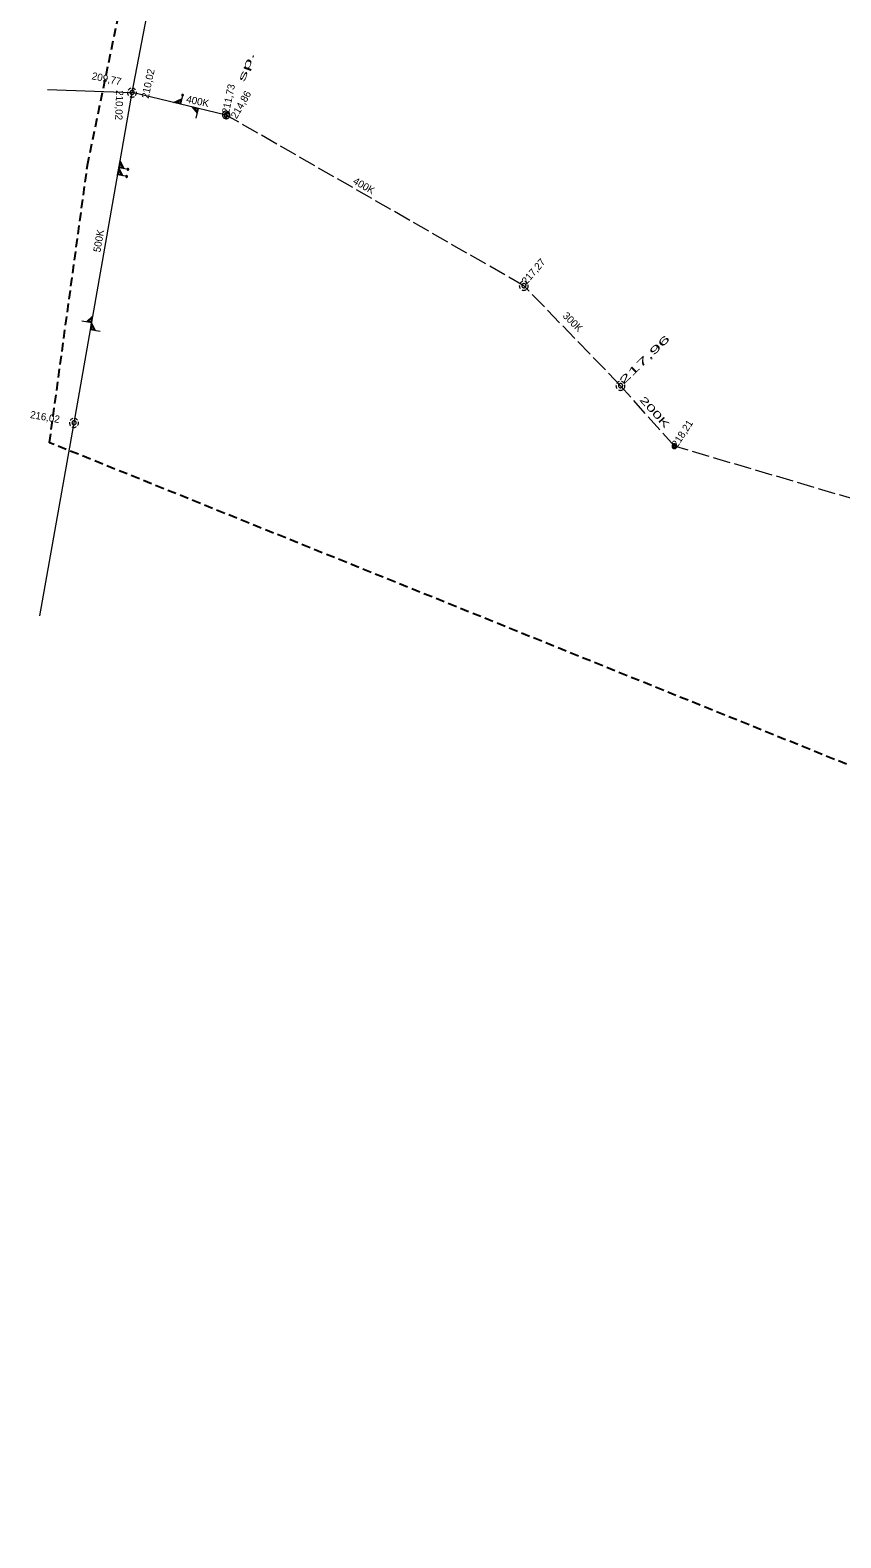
# Model space of a CAD drawing. Extents: x -739741 to -739027, y -1046215 to -1045797.
# Drawn here: x -739740.5 to -739651.7, y -1046072.8 to -1045907.7 of the extents above; entities that cross this region are included whole.
import ezdxf

# ---------------------------------------------------------------- set-up
doc = ezdxf.new("R2010")
doc.units = 0
doc.header["$LTSCALE"] = 0.32
doc.linetypes.add('LONG_DASHED', pattern=[7.5, 6, -1.5])
doc.linetypes.add('MEDIUM_DASHED', pattern=[4.5, 3, -1.5])
doc.layers.add('1', color=7, linetype='Continuous')
for name, color, linetype, lineweight in [('18', 7, 'Continuous', 13), ('20', 7, 'Continuous', 13), ('63', 7, 'MEDIUM_DASHED', 25)]:
    doc.layers.add(name, color=color, linetype=linetype, lineweight=lineweight)

msp = doc.modelspace()

# ---------------------------------------------------------------- linework, layer by layer
at = {"layer": '18'}
msp.add_line((-739719.059, -1045916.633), (-739719.059, -1045917.321), dxfattribs=at)
for points in [[(-739729.857, -1045914.429), (-739729.863, -1045914.506), (-739729.858, -1045914.583), (-739729.841, -1045914.658), (-739729.812, -1045914.729), (-739729.772, -1045914.795), (-739729.756, -1045914.817)], [(-739729.512, -1045914.037), (-739729.583, -1045914.065), (-739729.65, -1045914.104), (-739729.71, -1045914.152), (-739729.761, -1045914.209), (-739729.785, -1045914.243)], [(-739729.599, -1045914.946), (-739729.529, -1045914.977), (-739729.454, -1045914.996), (-739729.378, -1045915.003), (-739729.301, -1045914.998), (-739729.226, -1045914.981), (-739729.154, -1045914.953), (-739729.094, -1045914.918)], [(-739728.971, -1045914.22), (-739729.021, -1045914.162), (-739729.079, -1045914.112), (-739729.144, -1045914.071), (-739729.215, -1045914.042), (-739729.264, -1045914.028)], [(-739728.976, -1045914.806), (-739728.935, -1045914.741), (-739728.904, -1045914.671), (-739728.885, -1045914.596), (-739728.877, -1045914.52), (-739728.882, -1045914.443), (-739728.888, -1045914.408)], [(-739723.813, -1045914.693), (-739724.067, -1045915.758), (-739724.816, -1045915.579), (-739723.933, -1045915.196)], [(-739724.009, -1045915.299), (-739724.106, -1045915.704), (-739724.656, -1045915.572), (-739724.009, -1045915.298)], [(-739722.331, -1045917.302), (-739722.077, -1045916.236), (-739722.827, -1045916.057), (-739722.211, -1045916.798)], [(-739722.233, -1045916.672), (-739722.137, -1045916.267), (-739722.686, -1045916.136), (-739722.234, -1045916.673)], [(-739719.194, -1045917.147), (-739719.172, -1045917.18), (-739719.141, -1045917.205), (-739719.104, -1045917.219), (-739719.065, -1045917.222), (-739719.026, -1045917.213), (-739718.992, -1045917.193), (-739718.966, -1045917.163), (-739718.949, -1045917.127), (-739718.944, -1045917.088), (-739718.951, -1045917.049), (-739718.969, -1045917.014), (-739718.997, -1045916.986), (-739719.032, -1045916.967), (-739719.064, -1045916.96)], [(-739718.935, -1045916.78), (-739718.955, -1045916.747), (-739718.984, -1045916.721), (-739719.02, -1045916.704), (-739719.06, -1045916.7), (-739719.098, -1045916.707), (-739719.133, -1045916.726), (-739719.161, -1045916.754), (-739719.179, -1045916.789), (-739719.185, -1045916.828), (-739719.18, -1045916.867), (-739719.163, -1045916.903), (-739719.136, -1045916.932), (-739719.102, -1045916.951), (-739719.064, -1045916.96)], [(-739729.86, -1045923.711), (-739730.938, -1045923.521), (-739730.805, -1045922.763), (-739730.369, -1045923.621)], [(-739730.477, -1045923.552), (-739730.886, -1045923.48), (-739730.788, -1045922.922), (-739730.476, -1045923.552)], [(-739730.551, -1045923.491), (-739730.839, -1045923.44), (-739730.774, -1045923.074), (-739730.551, -1045923.492)], [(-739729.722, -1045922.927), (-739730.8, -1045922.737), (-739730.667, -1045921.979), (-739730.231, -1045922.837)], [(-739730.339, -1045922.768), (-739730.748, -1045922.696), (-739730.65, -1045922.138), (-739730.338, -1045922.768)], [(-739730.413, -1045922.707), (-739730.701, -1045922.656), (-739730.636, -1045922.29), (-739730.413, -1045922.708)], [(-739686.947, -1045935.589), (-739686.953, -1045935.666), (-739686.948, -1045935.743), (-739686.931, -1045935.818), (-739686.902, -1045935.889), (-739686.862, -1045935.955), (-739686.846, -1045935.977)], [(-739686.602, -1045935.197), (-739686.673, -1045935.225), (-739686.74, -1045935.264), (-739686.8, -1045935.312), (-739686.851, -1045935.369), (-739686.875, -1045935.403)], [(-739686.689, -1045936.106), (-739686.619, -1045936.137), (-739686.544, -1045936.156), (-739686.468, -1045936.163), (-739686.391, -1045936.158), (-739686.316, -1045936.141), (-739686.244, -1045936.113), (-739686.184, -1045936.078)], [(-739686.061, -1045935.38), (-739686.111, -1045935.322), (-739686.169, -1045935.272), (-739686.234, -1045935.231), (-739686.305, -1045935.202), (-739686.354, -1045935.188)], [(-739686.066, -1045935.966), (-739686.025, -1045935.901), (-739685.994, -1045935.831), (-739685.975, -1045935.756), (-739685.967, -1045935.68), (-739685.972, -1045935.603), (-739685.978, -1045935.568)], [(-739734.859, -1045939.504), (-739733.779, -1045939.694), (-739733.646, -1045938.935), (-739734.349, -1045939.594)], [(-739734.224, -1045939.564), (-739733.814, -1045939.636), (-739733.716, -1045939.08), (-739734.225, -1045939.564)], [(-739734.133, -1045939.532), (-739733.846, -1045939.583), (-739733.782, -1045939.217), (-739734.133, -1045939.533)], [(-739732.842, -1045940.671), (-739733.921, -1045940.481), (-739733.788, -1045939.723), (-739733.352, -1045940.581)], [(-739733.459, -1045940.512), (-739733.869, -1045940.44), (-739733.771, -1045939.882), (-739733.458, -1045940.512)], [(-739733.534, -1045940.451), (-739733.821, -1045940.401), (-739733.756, -1045940.034), (-739733.534, -1045940.452)], [(-739676.012, -1045946.147), (-739676.083, -1045946.175), (-739676.15, -1045946.214), (-739676.21, -1045946.262), (-739676.261, -1045946.319), (-739676.285, -1045946.353)], [(-739675.471, -1045946.33), (-739675.521, -1045946.272), (-739675.579, -1045946.222), (-739675.644, -1045946.181), (-739675.715, -1045946.152), (-739675.764, -1045946.138)], [(-739676.357, -1045946.539), (-739676.363, -1045946.616), (-739676.358, -1045946.693), (-739676.341, -1045946.768), (-739676.312, -1045946.839), (-739676.272, -1045946.905), (-739676.256, -1045946.927)], [(-739676.099, -1045947.056), (-739676.029, -1045947.087), (-739675.954, -1045947.106), (-739675.878, -1045947.113), (-739675.801, -1045947.108), (-739675.726, -1045947.091), (-739675.654, -1045947.063), (-739675.594, -1045947.028)], [(-739675.476, -1045946.916), (-739675.435, -1045946.851), (-739675.404, -1045946.781), (-739675.385, -1045946.706), (-739675.377, -1045946.63), (-739675.382, -1045946.553), (-739675.388, -1045946.518)], [(-739736.208, -1045950.599), (-739736.213, -1045950.676), (-739736.208, -1045950.753), (-739736.191, -1045950.828), (-739736.163, -1045950.899), (-739736.122, -1045950.965), (-739736.107, -1045950.987)], [(-739735.863, -1045950.207), (-739735.934, -1045950.235), (-739736, -1045950.274), (-739736.061, -1045950.322), (-739736.112, -1045950.379), (-739736.136, -1045950.413)], [(-739735.95, -1045951.116), (-739735.88, -1045951.147), (-739735.804, -1045951.166), (-739735.728, -1045951.173), (-739735.652, -1045951.168), (-739735.576, -1045951.151), (-739735.505, -1045951.123), (-739735.445, -1045951.088)], [(-739735.321, -1045950.39), (-739735.372, -1045950.332), (-739735.429, -1045950.282), (-739735.495, -1045950.241), (-739735.566, -1045950.212), (-739735.615, -1045950.198)], [(-739735.326, -1045950.976), (-739735.286, -1045950.911), (-739735.255, -1045950.841), (-739735.235, -1045950.766), (-739735.228, -1045950.69), (-739735.233, -1045950.613), (-739735.239, -1045950.578)]]:
    msp.add_lwpolyline(points, dxfattribs=at)
for points in [[(-739729.128, -1045914.489), (-739729.134, -1045914.437), (-739729.152, -1045914.387), (-739729.18, -1045914.343), (-739729.218, -1045914.306), (-739729.263, -1045914.279), (-739729.313, -1045914.263), (-739729.365, -1045914.258), (-739729.417, -1045914.265), (-739729.466, -1045914.284), (-739729.51, -1045914.314), (-739729.545, -1045914.353), (-739729.571, -1045914.398), (-739729.586, -1045914.449), (-739729.589, -1045914.501), (-739729.581, -1045914.553), (-739729.56, -1045914.601), (-739729.53, -1045914.644), (-739729.49, -1045914.679), (-739729.444, -1045914.703), (-739729.393, -1045914.717), (-739729.341, -1045914.719), (-739729.289, -1045914.709), (-739729.241, -1045914.687), (-739729.199, -1045914.655), (-739729.166, -1045914.615), (-739729.142, -1045914.568), (-739729.13, -1045914.517)], [(-739723.926, -1045914.763), (-739723.928, -1045914.796), (-739723.918, -1045914.829), (-739723.898, -1045914.855), (-739723.869, -1045914.872), (-739723.837, -1045914.879), (-739723.804, -1045914.873), (-739723.774, -1045914.857), (-739723.752, -1045914.831), (-739723.742, -1045914.8), (-739723.742, -1045914.767), (-739723.754, -1045914.735), (-739723.777, -1045914.71), (-739723.806, -1045914.695), (-739723.84, -1045914.69), (-739723.873, -1045914.698), (-739723.9, -1045914.717), (-739723.92, -1045914.744)], [(-739723.9, -1045914.77), (-739723.901, -1045914.799), (-739723.891, -1045914.825), (-739723.869, -1045914.843), (-739723.843, -1045914.853), (-739723.815, -1045914.85), (-739723.791, -1045914.835), (-739723.774, -1045914.813), (-739723.768, -1045914.785), (-739723.774, -1045914.758), (-739723.791, -1045914.736), (-739723.816, -1045914.721), (-739723.844, -1045914.719), (-739723.871, -1045914.729), (-739723.891, -1045914.748)], [(-739724.074, -1045915.37), (-739724.142, -1045915.654), (-739724.504, -1045915.568)], [(-739722.259, -1045916.579), (-739722.192, -1045916.296), (-739722.553, -1045916.21)], [(-739718.649, -1045916.95), (-739718.655, -1045916.88), (-739718.673, -1045916.813), (-739718.702, -1045916.749), (-739718.742, -1045916.691), (-739718.791, -1045916.64), (-739718.847, -1045916.599), (-739718.91, -1045916.567), (-739718.977, -1045916.547), (-739719.047, -1045916.539), (-739719.117, -1045916.542), (-739719.186, -1045916.558), (-739719.251, -1045916.585), (-739719.31, -1045916.622), (-739719.362, -1045916.669), (-739719.406, -1045916.725), (-739719.439, -1045916.786), (-739719.461, -1045916.853), (-739719.472, -1045916.922), (-739719.471, -1045916.993), (-739719.458, -1045917.062), (-739719.433, -1045917.127), (-739719.397, -1045917.188), (-739719.352, -1045917.242), (-739719.298, -1045917.287), (-739719.238, -1045917.322), (-739719.172, -1045917.347), (-739719.103, -1045917.36), (-739719.033, -1045917.361), (-739718.963, -1045917.35), (-739718.897, -1045917.328), (-739718.835, -1045917.295), (-739718.78, -1045917.251), (-739718.733, -1045917.199), (-739718.695, -1045917.14), (-739718.669, -1045917.075), (-739718.653, -1045917.006)], [(-739718.828, -1045916.949), (-739718.834, -1045916.897), (-739718.852, -1045916.847), (-739718.88, -1045916.803), (-739718.918, -1045916.766), (-739718.963, -1045916.739), (-739719.013, -1045916.723), (-739719.065, -1045916.718), (-739719.117, -1045916.725), (-739719.166, -1045916.744), (-739719.21, -1045916.774), (-739719.245, -1045916.813), (-739719.271, -1045916.858), (-739719.286, -1045916.909), (-739719.289, -1045916.961), (-739719.281, -1045917.013), (-739719.26, -1045917.061), (-739719.23, -1045917.104), (-739719.19, -1045917.139), (-739719.144, -1045917.163), (-739719.093, -1045917.177), (-739719.041, -1045917.179), (-739718.989, -1045917.169), (-739718.941, -1045917.147), (-739718.899, -1045917.115), (-739718.866, -1045917.075), (-739718.842, -1045917.028), (-739718.83, -1045916.977)], [(-739729.798, -1045922.818), (-739729.832, -1045922.818), (-739729.863, -1045922.83), (-739729.888, -1045922.852), (-739729.904, -1045922.881), (-739729.908, -1045922.914), (-739729.901, -1045922.947), (-739729.883, -1045922.976), (-739729.856, -1045922.995), (-739729.824, -1045923.004), (-739729.791, -1045923.002), (-739729.76, -1045922.988), (-739729.736, -1045922.964), (-739729.723, -1045922.933), (-739729.72, -1045922.899), (-739729.73, -1045922.867), (-739729.75, -1045922.841), (-739729.779, -1045922.823)], [(-739729.804, -1045922.844), (-739729.832, -1045922.845), (-739729.858, -1045922.857), (-739729.875, -1045922.879), (-739729.883, -1045922.906), (-739729.878, -1045922.935), (-739729.862, -1045922.958), (-739729.839, -1045922.973), (-739729.811, -1045922.977), (-739729.784, -1045922.969), (-739729.763, -1045922.951), (-739729.75, -1045922.926), (-739729.749, -1045922.897), (-739729.761, -1045922.871), (-739729.781, -1045922.852)], [(-739729.936, -1045923.602), (-739729.97, -1045923.602), (-739730.001, -1045923.614), (-739730.026, -1045923.636), (-739730.042, -1045923.665), (-739730.046, -1045923.698), (-739730.039, -1045923.731), (-739730.021, -1045923.76), (-739729.994, -1045923.779), (-739729.962, -1045923.788), (-739729.929, -1045923.786), (-739729.898, -1045923.772), (-739729.874, -1045923.748), (-739729.861, -1045923.717), (-739729.858, -1045923.683), (-739729.868, -1045923.651), (-739729.888, -1045923.625), (-739729.917, -1045923.607)], [(-739729.942, -1045923.628), (-739729.97, -1045923.629), (-739729.996, -1045923.641), (-739730.013, -1045923.663), (-739730.021, -1045923.69), (-739730.016, -1045923.719), (-739730, -1045923.742), (-739729.977, -1045923.757), (-739729.949, -1045923.761), (-739729.922, -1045923.753), (-739729.901, -1045923.735), (-739729.888, -1045923.71), (-739729.887, -1045923.681), (-739729.899, -1045923.655), (-739729.919, -1045923.636)], [(-739686.218, -1045935.649), (-739686.224, -1045935.597), (-739686.242, -1045935.547), (-739686.27, -1045935.503), (-739686.308, -1045935.466), (-739686.353, -1045935.439), (-739686.403, -1045935.423), (-739686.455, -1045935.418), (-739686.507, -1045935.425), (-739686.556, -1045935.444), (-739686.6, -1045935.474), (-739686.635, -1045935.513), (-739686.661, -1045935.558), (-739686.676, -1045935.609), (-739686.679, -1045935.661), (-739686.671, -1045935.713), (-739686.65, -1045935.761), (-739686.62, -1045935.804), (-739686.58, -1045935.839), (-739686.534, -1045935.863), (-739686.483, -1045935.877), (-739686.431, -1045935.879), (-739686.379, -1045935.869), (-739686.331, -1045935.847), (-739686.289, -1045935.815), (-739686.256, -1045935.775), (-739686.232, -1045935.728), (-739686.22, -1045935.677)], [(-739675.628, -1045946.599), (-739675.634, -1045946.547), (-739675.652, -1045946.497), (-739675.68, -1045946.453), (-739675.718, -1045946.416), (-739675.763, -1045946.389), (-739675.813, -1045946.373), (-739675.865, -1045946.368), (-739675.917, -1045946.375), (-739675.966, -1045946.394), (-739676.01, -1045946.424), (-739676.045, -1045946.463), (-739676.071, -1045946.508), (-739676.086, -1045946.559), (-739676.089, -1045946.611), (-739676.081, -1045946.663), (-739676.06, -1045946.711), (-739676.03, -1045946.754), (-739675.99, -1045946.789), (-739675.944, -1045946.813), (-739675.893, -1045946.827), (-739675.841, -1045946.829), (-739675.789, -1045946.819), (-739675.741, -1045946.797), (-739675.699, -1045946.765), (-739675.666, -1045946.725), (-739675.642, -1045946.678), (-739675.63, -1045946.627)], [(-739735.478, -1045950.659), (-739735.485, -1045950.607), (-739735.502, -1045950.557), (-739735.531, -1045950.513), (-739735.569, -1045950.476), (-739735.614, -1045950.449), (-739735.664, -1045950.433), (-739735.716, -1045950.428), (-739735.767, -1045950.435), (-739735.816, -1045950.454), (-739735.86, -1045950.484), (-739735.896, -1045950.523), (-739735.922, -1045950.568), (-739735.936, -1045950.619), (-739735.94, -1045950.671), (-739735.931, -1045950.723), (-739735.911, -1045950.771), (-739735.88, -1045950.814), (-739735.841, -1045950.849), (-739735.794, -1045950.873), (-739735.744, -1045950.887), (-739735.691, -1045950.889), (-739735.64, -1045950.879), (-739735.592, -1045950.857), (-739735.549, -1045950.825), (-739735.517, -1045950.785), (-739735.493, -1045950.738), (-739735.48, -1045950.687)], [(-739669.696, -1045953.227), (-739669.701, -1045953.171), (-739669.718, -1045953.118), (-739669.747, -1045953.069), (-739669.786, -1045953.028), (-739669.831, -1045952.996), (-739669.884, -1045952.974), (-739669.939, -1045952.963), (-739669.995, -1045952.965), (-739670.049, -1045952.978), (-739670.1, -1045953.003), (-739670.145, -1045953.038), (-739670.181, -1045953.081), (-739670.206, -1045953.131), (-739670.221, -1045953.186), (-739670.223, -1045953.242), (-739670.215, -1045953.297), (-739670.194, -1045953.35), (-739670.163, -1045953.396), (-739670.122, -1045953.435), (-739670.075, -1045953.465), (-739670.022, -1045953.484), (-739669.966, -1045953.491), (-739669.909, -1045953.487), (-739669.855, -1045953.47), (-739669.806, -1045953.443), (-739669.765, -1045953.405), (-739669.732, -1045953.36), (-739669.708, -1045953.309), (-739669.696, -1045953.254)], [(-739669.755, -1045953.23), (-739669.761, -1045953.181), (-739669.779, -1045953.135), (-739669.806, -1045953.094), (-739669.843, -1045953.061), (-739669.887, -1045953.039), (-739669.936, -1045953.027), (-739669.985, -1045953.027), (-739670.032, -1045953.039), (-739670.076, -1045953.062), (-739670.114, -1045953.095), (-739670.142, -1045953.136), (-739670.159, -1045953.183), (-739670.164, -1045953.232), (-739670.157, -1045953.281), (-739670.14, -1045953.327), (-739670.112, -1045953.367), (-739670.075, -1045953.4), (-739670.031, -1045953.422), (-739669.982, -1045953.434), (-739669.933, -1045953.433), (-739669.885, -1045953.421), (-739669.842, -1045953.397), (-739669.804, -1045953.364), (-739669.777, -1045953.323), (-739669.761, -1045953.276)], [(-739669.814, -1045953.234), (-739669.82, -1045953.192), (-739669.837, -1045953.154), (-739669.865, -1045953.123), (-739669.899, -1045953.1), (-739669.94, -1045953.089), (-739669.982, -1045953.089), (-739670.022, -1045953.101), (-739670.056, -1045953.124), (-739670.083, -1045953.156), (-739670.1, -1045953.194), (-739670.105, -1045953.235), (-739670.1, -1045953.277), (-739670.081, -1045953.314), (-739670.054, -1045953.346), (-739670.017, -1045953.368), (-739669.978, -1045953.379), (-739669.936, -1045953.378), (-739669.896, -1045953.365), (-739669.862, -1045953.342), (-739669.835, -1045953.309), (-739669.819, -1045953.271)]]:
    msp.add_lwpolyline(points, close=True, dxfattribs=at)
at = {"layer": '20'}
for p, q in [((-739738.629, -1045914.17), (-739729.359, -1045914.5)), ((-739738.629, -1045914.17), (-739729.359, -1045914.5)), ((-739735.71, -1045950.67), (-739729.359, -1045914.5)), ((-739735.71, -1045950.67), (-739729.359, -1045914.5)), ((-739739.449, -1045971.81), (-739735.71, -1045950.67)), ((-739739.449, -1045971.81), (-739735.71, -1045950.67))]:
    msp.add_line(p, q, dxfattribs=at)
msp.add_lwpolyline([(-739719.059, -1045916.96), (-739729.359, -1045914.5), (-739723.219, -1045882.53), (-739714.69, -1045845.12)], dxfattribs=at)
msp.add_lwpolyline([(-739719.059, -1045916.96), (-739729.359, -1045914.5), (-739723.219, -1045882.53), (-739714.69, -1045845.12)], dxfattribs=at)
at = {"layer": '20', "linetype": 'LONG_DASHED'}
for points in [[(-739675.859, -1045946.61), (-739686.449, -1045935.66), (-739719.059, -1045916.96)], [(-739675.859, -1045946.61), (-739686.449, -1045935.66), (-739719.059, -1045916.96)], [(-739624.719, -1045966.57), (-739669.96, -1045953.24), (-739675.859, -1045946.61)], [(-739624.719, -1045966.57), (-739669.96, -1045953.24), (-739675.859, -1045946.61)]]:
    msp.add_lwpolyline(points, dxfattribs=at)
at = {"layer": '63'}
msp.add_lwpolyline([(-739088.915, -1046214.93), (-739738.392, -1045952.844), (-739738.394, -1045952.843), (-739738.395, -1045952.842), (-739738.397, -1045952.841), (-739738.398, -1045952.839), (-739738.398, -1045952.837), (-739738.398, -1045952.835), (-739738.398, -1045952.833), (-739734.244, -1045922.471), (-739734.244, -1045922.47), (-739711.46, -1045812.716), (-739711.459, -1045812.714), (-739711.458, -1045812.713), (-739711.457, -1045812.711), (-739711.456, -1045812.71), (-739711.454, -1045812.709), (-739711.452, -1045812.709), (-739711.45, -1045812.708), (-739711.448, -1045812.708), (-739711.447, -1045812.709), (-739026.908, -1046056.391)], dxfattribs=at)

# ---------------------------------------------------------------- texts
at = {"layer": '1'}
for s, rotation, width, p in [('sp. ', 70, 2.35, (-739717.065, -1045913.398)), ('217,96', 44, 2.2, (-739675.562, -1045946.545)), ('200K', 312, 1.7, (-739673.843, -1045948.184))]:
    msp.add_text(s, height=0.8, rotation=rotation, dxfattribs=dict(at, width=width)).set_placement(p)
for s, rotation, p in [('209,77', 348, (-739733.826, -1045913.037)), ('210,02', 78, (-739727.556, -1045915.207)), ('210,02', 268, (-739731.104, -1045914.23)), ('400K', 348, (-739723.474, -1045915.579)), ('211,73', 78, (-739718.752, -1045916.868)), ('214,86', 60, (-739717.915, -1045917.437)), ('400K', 330, (-739705.245, -1045924.422)), ('500K', 80, (-739732.84, -1045932.039)), ('217,27', 49, (-739686.168, -1045935.581)), ('300K', 315, (-739682.264, -1045939.019)), ('216,02', 350, (-739740.574, -1045950.135)), ('218,21', 57, (-739669.653, -1045953.427))]:
    msp.add_text(s, height=0.8, rotation=rotation, dxfattribs=at).set_placement(p)

doc.saveas('drawing.dxf')
